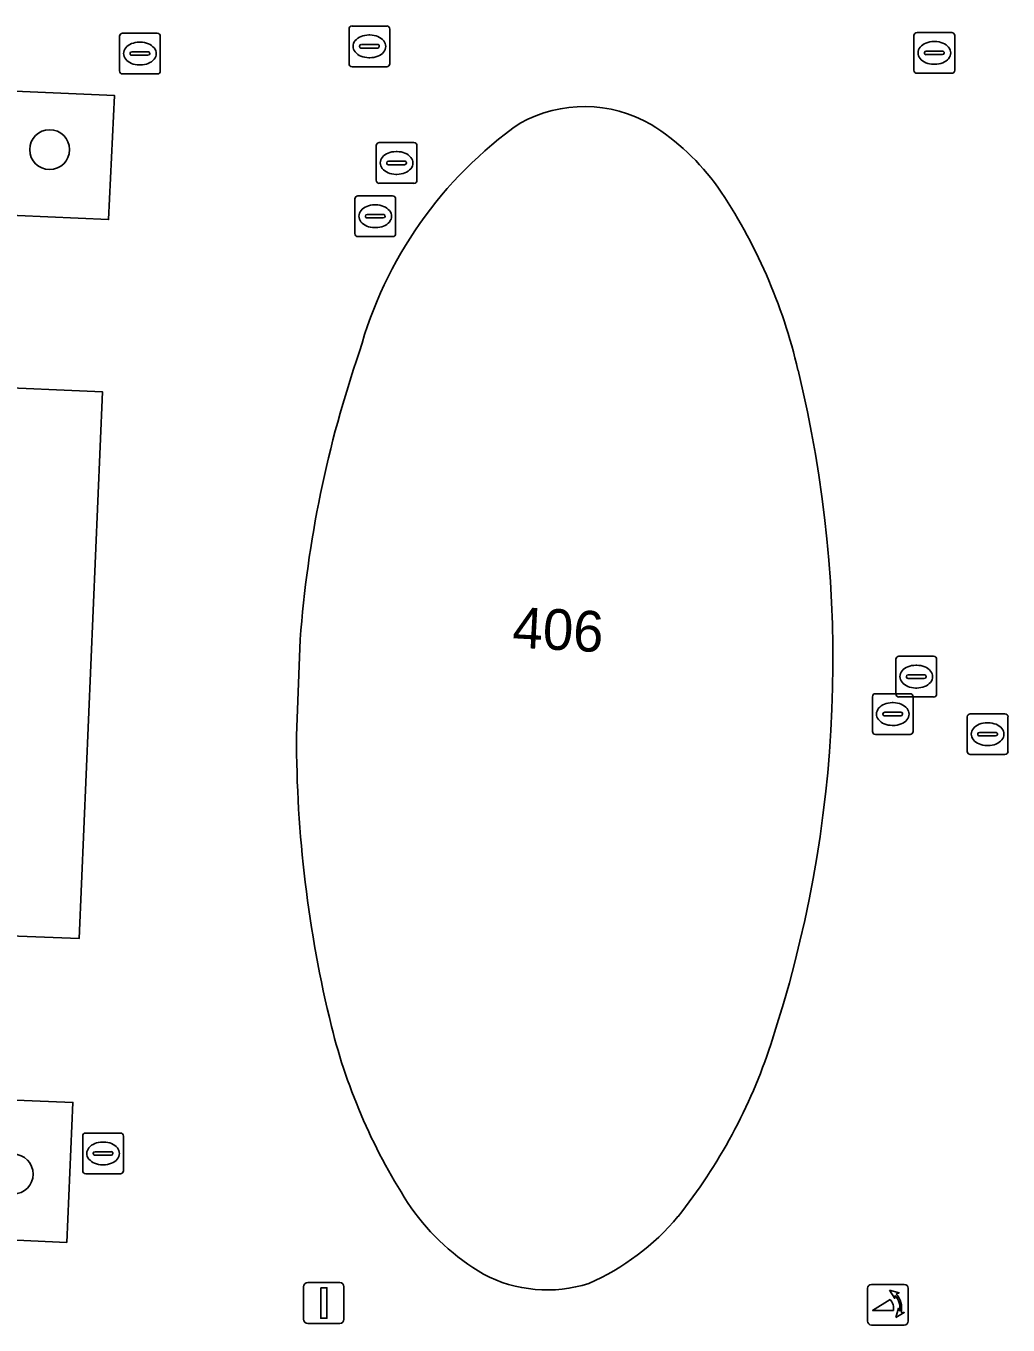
# Model space of a CAD drawing. Extents: x 160888 to 161385, y 386490 to 386908.
# Drawn here: x 161040.48 to 161064.6, y 386705.3 to 386737.22 of the extents above; entities that cross this region are included whole.
import ezdxf

# ---------------------------------------------------------------- set-up
doc = ezdxf.new("R2010")
doc.units = 0
for name, color, linetype in [('IMGEO_Boom', 7, 'Continuous'), ('IMGEO_Groenvoorziening', 7, 'Continuous'), ('IMGEO_Kolk', 7, 'Continuous'), ('IMGEO_Lichtmast', 7, 'Continuous'), ('IMGEO_Pand', 7, 'Continuous'), ('IMGEO_Pand_nummerreeks', 7, 'Continuous'), ('IMGEO_Poller', 7, 'Continuous'), ('IMGEO_Rioolput', 7, 'Continuous'), ('IMGEO_Voetpad_open', 7, 'Continuous')]:
    doc.layers.add(name, color=color, linetype=linetype)

msp = doc.modelspace()

# ---------------------------------------------------------------- linework, layer by layer
at = {"layer": 'IMGEO_Boom'}
for centre in [(161041.064, 386734.18), (161040.172, 386709.011)]:
    msp.add_circle(centre, 0.489, dxfattribs=at)
at = {"layer": 'IMGEO_Groenvoorziening'}
for points in [[(161039.526, 386732.596), (161042.513, 386732.464), (161042.656, 386735.511), (161039.638, 386735.641)], [(161038.802, 386714.912), (161041.789, 386714.797), (161042.363, 386728.229), (161039.349, 386728.359)], [(161038.486, 386707.47), (161041.484, 386707.334), (161041.637, 386710.771), (161038.63, 386710.889)]]:
    msp.add_lwpolyline(points, close=True, dxfattribs=at)
at = {"layer": 'IMGEO_Kolk'}
for p, q in [((161048.492, 386737.218), (161049.344, 386737.218)), ((161048.417, 386736.292), (161048.417, 386737.144)), ((161048.905, 386736.998), (161048.93, 386736.998)), ((161049.418, 386737.144), (161049.418, 386736.292)), ((161062.29, 386736.131), (161062.29, 386736.983)), ((161062.365, 386737.057), (161063.217, 386737.057)), ((161063.291, 386736.983), (161063.291, 386736.131)), ((161048.676, 386736.712), (161048.676, 386736.724)), ((161049.114, 386736.675), (161048.716, 386736.675)), ((161048.719, 386736.761), (161049.117, 386736.761)), ((161049.16, 386736.724), (161049.16, 386736.712)), ((161062.549, 386736.551), (161062.549, 386736.563)), ((161062.592, 386736.6), (161062.99, 386736.6)), ((161062.778, 386736.837), (161062.803, 386736.837)), ((161063.033, 386736.563), (161063.033, 386736.551)), ((161048.928, 386736.438), (161048.903, 386736.438)), ((161062.987, 386736.514), (161062.589, 386736.514)), ((161062.801, 386736.277), (161062.776, 386736.277)), ((161049.344, 386736.218), (161048.492, 386736.218)), ((161063.217, 386736.057), (161062.365, 386736.057)), ((161061.269, 386719.888), (161061.269, 386720.74)), ((161061.344, 386720.814), (161062.196, 386720.814)), ((161061.757, 386720.594), (161061.782, 386720.594)), ((161062.27, 386720.74), (161062.27, 386719.888)), ((161061.528, 386720.308), (161061.528, 386720.32)), ((161061.966, 386720.271), (161061.568, 386720.271)), ((161061.571, 386720.357), (161061.969, 386720.357)), ((161062.012, 386720.32), (161062.012, 386720.308)), ((161061.78, 386720.034), (161061.755, 386720.034)), ((161062.196, 386719.814), (161061.344, 386719.814))]:
    msp.add_line(p, q, dxfattribs=at)
for points in [[(161048.492, 386737.218), (161049.344, 386737.218)], [(161048.417, 386736.292), (161048.417, 386737.144)], [(161049.418, 386737.144), (161049.418, 386736.292)], [(161062.29, 386736.131), (161062.29, 386736.983)], [(161062.365, 386737.057), (161063.217, 386737.057)], [(161063.291, 386736.983), (161063.291, 386736.131)], [(161049.344, 386736.218), (161048.492, 386736.218)], [(161063.217, 386736.057), (161062.365, 386736.057)], [(161061.269, 386719.888), (161061.269, 386720.74)], [(161061.344, 386720.814), (161062.196, 386720.814)], [(161062.27, 386720.74), (161062.27, 386719.888)], [(161062.196, 386719.814), (161061.344, 386719.814)]]:
    msp.add_lwpolyline(points, dxfattribs=at)
for centre, radius, start, end in [((161048.494, 386737.142), 0.0765, 91.552, 178.448), ((161048.494, 386737.142), 0.0765, 91.552, 178.448), ((161049.342, 386737.142), 0.0765, 1.552, 88.448), ((161049.342, 386737.142), 0.0765, 1.552, 88.448), ((161062.367, 386736.981), 0.0765, 91.552, 178.448), ((161062.367, 386736.981), 0.0765, 91.552, 178.448), ((161063.215, 386736.981), 0.0765, 1.552, 88.448), ((161063.215, 386736.981), 0.0765, 1.552, 88.448), ((161048.716, 386736.721), 0.0403, 85.8775, 175.7526), ((161048.713, 386736.711), 0.0366, 178.938, 274.7102), ((161049.117, 386736.718), 0.043, 264.8664, 352.4533), ((161049.121, 386736.723), 0.0386, 1.7309, 96.639), ((161062.589, 386736.56), 0.0403, 85.8775, 175.7526), ((161062.586, 386736.55), 0.0366, 178.938, 274.7102), ((161062.99, 386736.557), 0.043, 264.8664, 352.4533), ((161062.994, 386736.562), 0.0386, 1.7309, 96.639), ((161048.494, 386736.294), 0.0765, 181.552, 268.448), ((161048.494, 386736.294), 0.0765, 181.552, 268.448), ((161049.342, 386736.294), 0.0765, 271.552, 358.448), ((161049.342, 386736.294), 0.0765, 271.552, 358.448), ((161062.367, 386736.133), 0.0765, 181.552, 268.448), ((161062.367, 386736.133), 0.0765, 181.552, 268.448), ((161063.215, 386736.133), 0.0765, 271.552, 358.448), ((161063.215, 386736.133), 0.0765, 271.552, 358.448), ((161061.346, 386720.738), 0.0765, 91.552, 178.448), ((161061.346, 386720.738), 0.0765, 91.552, 178.448), ((161062.194, 386720.738), 0.0765, 1.552, 88.448), ((161062.194, 386720.738), 0.0765, 1.552, 88.448), ((161061.568, 386720.317), 0.0403, 85.8775, 175.7526), ((161061.565, 386720.307), 0.0366, 178.938, 274.7102), ((161061.969, 386720.314), 0.043, 264.8664, 352.4533), ((161061.973, 386720.319), 0.0386, 1.7309, 96.639), ((161061.346, 386719.89), 0.0765, 181.552, 268.448), ((161061.346, 386719.89), 0.0765, 181.552, 268.448), ((161062.194, 386719.89), 0.0765, 271.552, 358.448), ((161062.194, 386719.89), 0.0765, 271.552, 358.448)]:
    msp.add_arc(centre, radius, start, end, dxfattribs=at)
for centre, major_axis, ratio, start_param, end_param in [((161048.904, 386736.718), (-0.387, 0.002), 0.722429, 4.712389, 7.853982), ((161048.929, 386736.718), (-0.39, 0.002), 0.717154, 1.570796, 4.712389), ((161062.777, 386736.557), (-0.387, 0.002), 0.722429, 4.712389, 7.853982), ((161062.802, 386736.557), (-0.39, 0.002), 0.717154, 1.570796, 4.712389), ((161061.756, 386720.314), (-0.387, 0.002), 0.722429, 4.712389, 7.853982), ((161061.781, 386720.314), (-0.39, 0.002), 0.717154, 1.570796, 4.712389)]:
    msp.add_ellipse(centre, major_axis=major_axis, ratio=ratio, start_param=start_param, end_param=end_param, dxfattribs=at)
at = {"layer": 'IMGEO_Lichtmast'}
for p, q in [((161047.302, 386705.444), (161047.302, 386706.244)), ((161047.302, 386706.244), (161047.302, 386705.444)), ((161047.402, 386706.344), (161048.192, 386706.344)), ((161048.192, 386706.344), (161047.402, 386706.344)), ((161048.292, 386706.244), (161048.292, 386705.444)), ((161048.292, 386705.444), (161048.292, 386706.244)), ((161048.192, 386705.344), (161047.402, 386705.344)), ((161047.402, 386705.344), (161048.192, 386705.344))]:
    msp.add_line(p, q, dxfattribs=at)
msp.add_lwpolyline([(161047.722, 386706.219), (161047.872, 386706.219), (161047.872, 386705.469), (161047.722, 386705.469), (161047.722, 386706.219)], dxfattribs=at)
for centre, start, end in [((161047.402, 386706.244), 90, 180), ((161047.402, 386706.244), 90, 180), ((161048.192, 386706.244), 0, 90), ((161048.192, 386706.244), 360, 90), ((161047.402, 386705.444), 180, 270), ((161047.402, 386705.444), 180, 270), ((161048.192, 386705.444), 270, 0), ((161048.192, 386705.444), 270, 0)]:
    msp.add_arc(centre, 0.1, start, end, dxfattribs=at)
at = {"layer": 'IMGEO_Pand'}
msp.add_lwpolyline([(161047.22, 386722.145), (161047.127, 386719.777)], dxfattribs=at)
for centre, radius, start, end in [((161054.196, 386731.963), 3.275, 59.9847, 118.8039), ((161058.492, 386726.517), 10.182, 125.2343, 164.6202), ((161052.785, 386729.913), 5.759, 35.5324, 58.0373), ((161046.426, 386725.74), 13.363, 13.0848, 34.2475), ((161074.964, 386720.123), 27.818, 160.9175, 175.8307), ((161030.326, 386721.647), 29.974, 341.6232, 13.7384), ((161077.018, 386719.752), 29.891, 179.953, 193.7693), ((161061.976, 386716.123), 14.418, 193.9898, 213.4039), ((161045.912, 386716.393), 13.527, 321.4821, 341.9293), ((161054.654, 386711.527), 5.778, 215.3302, 239.4389), ((161051.945, 386711.745), 5.912, 293.5352, 320.3134), ((161053.283, 386709.533), 3.368, 242.2634, 287.6749)]:
    msp.add_arc(centre, radius, start, end, dxfattribs=at)
at = {"layer": 'IMGEO_Poller'}
for p, q in [((161062.053, 386706.3), (161061.245, 386706.3)), ((161062.053, 386706.3), (161061.245, 386706.3)), ((161061.151, 386706.205), (161061.151, 386705.398)), ((161061.151, 386706.205), (161061.151, 386705.398)), ((161062.147, 386705.398), (161062.147, 386706.205)), ((161062.147, 386705.398), (161062.147, 386706.205)), ((161061.245, 386705.303), (161062.053, 386705.303)), ((161061.245, 386705.303), (161062.053, 386705.303))]:
    msp.add_line(p, q, dxfattribs=at)
for points in [[(161061.786, 386705.656), (161061.273, 386705.656), (161061.703, 386705.931)], [(161061.83, 386706.029), (161061.818, 386705.956), (161061.693, 386706.161)], [(161061.693, 386706.161), (161061.924, 386706.095), (161061.853, 386706.063)], [(161061.846, 386705.484), (161061.912, 386705.715), (161061.942, 386705.647)], [(161061.978, 386705.62), (161062.05, 386705.609), (161061.846, 386705.484)]]:
    msp.add_lwpolyline(points, dxfattribs=at)
for centre, radius, start, end in [((161061.245, 386706.205), 0.0946, 90, 180), ((161061.245, 386706.205), 0.0946, 90, 180), ((161062.053, 386706.205), 0.0946, 0, 90), ((161062.053, 386706.205), 0.0946, 0, 90), ((161061.458, 386705.706), 0.332, 351.3247, 42.4854), ((161061.472, 386705.716), 0.476, 351.7527, 41.1691), ((161061.472, 386705.716), 0.516, 349.3569, 42.2912), ((161061.245, 386705.398), 0.0946, 180, 270), ((161061.245, 386705.398), 0.0946, 180, 270), ((161062.053, 386705.398), 0.0946, 270, 0), ((161062.053, 386705.398), 0.0946, 270, 0)]:
    msp.add_arc(centre, radius, start, end, dxfattribs=at)
at = {"layer": 'IMGEO_Rioolput'}
for p, q in [((161042.781, 386736.115), (161042.781, 386736.967)), ((161042.856, 386737.041), (161043.708, 386737.041)), ((161043.782, 386736.967), (161043.782, 386736.115)), ((161043.04, 386736.535), (161043.04, 386736.547)), ((161043.083, 386736.584), (161043.481, 386736.584)), ((161043.269, 386736.821), (161043.294, 386736.821)), ((161043.524, 386736.547), (161043.524, 386736.535)), ((161043.478, 386736.498), (161043.08, 386736.498)), ((161043.292, 386736.261), (161043.267, 386736.261)), ((161043.708, 386736.041), (161042.856, 386736.041)), ((161049.158, 386734.353), (161050.01, 386734.353)), ((161049.083, 386733.427), (161049.083, 386734.279)), ((161049.571, 386734.133), (161049.596, 386734.133)), ((161050.084, 386734.279), (161050.084, 386733.427)), ((161049.342, 386733.847), (161049.342, 386733.859)), ((161049.78, 386733.81), (161049.382, 386733.81)), ((161049.385, 386733.896), (161049.783, 386733.896)), ((161049.826, 386733.859), (161049.826, 386733.847)), ((161049.594, 386733.573), (161049.569, 386733.573)), ((161048.634, 386733.044), (161049.486, 386733.044)), ((161050.01, 386733.353), (161049.158, 386733.353)), ((161048.559, 386732.118), (161048.559, 386732.97)), ((161049.047, 386732.824), (161049.072, 386732.824)), ((161049.56, 386732.97), (161049.56, 386732.118)), ((161048.818, 386732.538), (161048.818, 386732.55)), ((161049.256, 386732.501), (161048.858, 386732.501)), ((161048.861, 386732.587), (161049.259, 386732.587)), ((161049.302, 386732.55), (161049.302, 386732.538)), ((161049.07, 386732.264), (161049.045, 386732.264)), ((161049.486, 386732.044), (161048.634, 386732.044)), ((161061.846, 386720.807), (161061.846, 386721.659)), ((161061.921, 386721.733), (161062.773, 386721.733)), ((161062.847, 386721.659), (161062.847, 386720.807)), ((161062.105, 386721.227), (161062.105, 386721.239)), ((161062.148, 386721.276), (161062.546, 386721.276)), ((161062.334, 386721.513), (161062.359, 386721.513)), ((161062.589, 386721.239), (161062.589, 386721.227)), ((161062.543, 386721.19), (161062.145, 386721.19)), ((161062.357, 386720.953), (161062.332, 386720.953)), ((161062.773, 386720.733), (161061.921, 386720.733)), ((161063.673, 386720.32), (161064.525, 386720.32)), ((161063.598, 386719.394), (161063.598, 386720.246)), ((161064.086, 386720.1), (161064.111, 386720.1)), ((161064.599, 386720.246), (161064.599, 386719.394)), ((161063.857, 386719.814), (161063.857, 386719.826)), ((161064.295, 386719.777), (161063.897, 386719.777)), ((161063.9, 386719.863), (161064.298, 386719.863)), ((161064.341, 386719.826), (161064.341, 386719.814)), ((161064.525, 386719.32), (161063.673, 386719.32)), ((161064.109, 386719.54), (161064.084, 386719.54)), ((161041.877, 386709.093), (161041.877, 386709.945)), ((161041.952, 386710.019), (161042.804, 386710.019)), ((161042.365, 386709.799), (161042.39, 386709.799)), ((161042.878, 386709.945), (161042.878, 386709.093)), ((161042.136, 386709.513), (161042.136, 386709.525)), ((161042.574, 386709.476), (161042.176, 386709.476)), ((161042.179, 386709.562), (161042.577, 386709.562)), ((161042.62, 386709.525), (161042.62, 386709.513)), ((161042.388, 386709.239), (161042.363, 386709.239)), ((161042.804, 386709.019), (161041.952, 386709.019))]:
    msp.add_line(p, q, dxfattribs=at)
for points in [[(161042.781, 386736.115), (161042.781, 386736.967)], [(161042.856, 386737.041), (161043.708, 386737.041)], [(161043.782, 386736.967), (161043.782, 386736.115)], [(161043.708, 386736.041), (161042.856, 386736.041)], [(161049.158, 386734.353), (161050.01, 386734.353)], [(161049.083, 386733.427), (161049.083, 386734.279)], [(161050.084, 386734.279), (161050.084, 386733.427)], [(161048.634, 386733.044), (161049.486, 386733.044)], [(161050.01, 386733.353), (161049.158, 386733.353)], [(161048.559, 386732.118), (161048.559, 386732.97)], [(161049.56, 386732.97), (161049.56, 386732.118)], [(161049.486, 386732.044), (161048.634, 386732.044)], [(161061.846, 386720.807), (161061.846, 386721.659)], [(161061.921, 386721.733), (161062.773, 386721.733)], [(161062.847, 386721.659), (161062.847, 386720.807)], [(161062.773, 386720.733), (161061.921, 386720.733)], [(161063.673, 386720.32), (161064.525, 386720.32)], [(161063.598, 386719.394), (161063.598, 386720.246)], [(161064.599, 386720.246), (161064.599, 386719.394)], [(161064.525, 386719.32), (161063.673, 386719.32)], [(161041.877, 386709.093), (161041.877, 386709.945)], [(161041.952, 386710.019), (161042.804, 386710.019)], [(161042.878, 386709.945), (161042.878, 386709.093)], [(161042.804, 386709.019), (161041.952, 386709.019)]]:
    msp.add_lwpolyline(points, dxfattribs=at)
for centre, radius, start, end in [((161042.858, 386736.965), 0.0765, 91.552, 178.448), ((161042.858, 386736.965), 0.0765, 91.552, 178.448), ((161043.706, 386736.965), 0.0765, 1.552, 88.448), ((161043.706, 386736.965), 0.0765, 1.552, 88.448), ((161043.08, 386736.544), 0.0403, 85.8775, 175.7526), ((161043.485, 386736.546), 0.0386, 1.7309, 96.639), ((161043.077, 386736.534), 0.0366, 178.938, 274.7102), ((161043.481, 386736.541), 0.043, 264.8664, 352.4533), ((161042.858, 386736.117), 0.0765, 181.552, 268.448), ((161042.858, 386736.117), 0.0765, 181.552, 268.448), ((161043.706, 386736.117), 0.0765, 271.552, 358.448), ((161043.706, 386736.117), 0.0765, 271.552, 358.448), ((161049.16, 386734.277), 0.0765, 91.552, 178.448), ((161049.16, 386734.277), 0.0765, 91.552, 178.448), ((161050.008, 386734.277), 0.0765, 1.552, 88.448), ((161050.008, 386734.277), 0.0765, 1.552, 88.448), ((161049.382, 386733.856), 0.0403, 85.8775, 175.7526), ((161049.379, 386733.846), 0.0366, 178.938, 274.7102), ((161049.783, 386733.853), 0.043, 264.8664, 352.4533), ((161049.787, 386733.858), 0.0386, 1.7309, 96.639), ((161049.16, 386733.429), 0.0765, 181.552, 268.448), ((161049.16, 386733.429), 0.0765, 181.552, 268.448), ((161050.008, 386733.429), 0.0765, 271.552, 358.448), ((161050.008, 386733.429), 0.0765, 271.552, 358.448), ((161048.636, 386732.968), 0.0765, 91.552, 178.448), ((161048.636, 386732.968), 0.0765, 91.552, 178.448), ((161049.484, 386732.968), 0.0765, 1.552, 88.448), ((161049.484, 386732.968), 0.0765, 1.552, 88.448), ((161048.858, 386732.547), 0.0403, 85.8775, 175.7526), ((161048.855, 386732.537), 0.0366, 178.938, 274.7102), ((161049.259, 386732.544), 0.043, 264.8664, 352.4533), ((161049.263, 386732.549), 0.0386, 1.7309, 96.639), ((161048.636, 386732.12), 0.0765, 181.552, 268.448), ((161048.636, 386732.12), 0.0765, 181.552, 268.448), ((161049.484, 386732.12), 0.0765, 271.552, 358.448), ((161049.484, 386732.12), 0.0765, 271.552, 358.448), ((161061.923, 386721.657), 0.0765, 91.552, 178.448), ((161061.923, 386721.657), 0.0765, 91.552, 178.448), ((161062.771, 386721.657), 0.0765, 1.552, 88.448), ((161062.771, 386721.657), 0.0765, 1.552, 88.448), ((161062.145, 386721.236), 0.0403, 85.8775, 175.7526), ((161062.55, 386721.238), 0.0386, 1.7309, 96.639), ((161062.142, 386721.226), 0.0366, 178.938, 274.7102), ((161062.546, 386721.233), 0.043, 264.8664, 352.4533), ((161061.923, 386720.809), 0.0765, 181.552, 268.448), ((161061.923, 386720.809), 0.0765, 181.552, 268.448), ((161062.771, 386720.809), 0.0765, 271.552, 358.448), ((161062.771, 386720.809), 0.0765, 271.552, 358.448), ((161063.675, 386720.244), 0.0765, 91.552, 178.448), ((161063.675, 386720.244), 0.0765, 91.552, 178.448), ((161064.523, 386720.244), 0.0765, 1.552, 88.448), ((161064.523, 386720.244), 0.0765, 1.552, 88.448), ((161063.897, 386719.823), 0.0403, 85.8775, 175.7526), ((161063.894, 386719.813), 0.0366, 178.938, 274.7102), ((161064.298, 386719.82), 0.043, 264.8664, 352.4533), ((161064.302, 386719.825), 0.0386, 1.7309, 96.639), ((161063.675, 386719.396), 0.0765, 181.552, 268.448), ((161063.675, 386719.396), 0.0765, 181.552, 268.448), ((161064.523, 386719.396), 0.0765, 271.552, 358.448), ((161064.523, 386719.396), 0.0765, 271.552, 358.448), ((161041.954, 386709.943), 0.0765, 91.552, 178.448), ((161041.954, 386709.943), 0.0765, 91.552, 178.448), ((161042.802, 386709.943), 0.0765, 1.552, 88.448), ((161042.802, 386709.943), 0.0765, 1.552, 88.448), ((161042.176, 386709.522), 0.0403, 85.8775, 175.7526), ((161042.173, 386709.512), 0.0366, 178.938, 274.7102), ((161042.577, 386709.519), 0.043, 264.8664, 352.4533), ((161042.581, 386709.524), 0.0386, 1.7309, 96.639), ((161041.954, 386709.095), 0.0765, 181.552, 268.448), ((161041.954, 386709.095), 0.0765, 181.552, 268.448), ((161042.802, 386709.095), 0.0765, 271.552, 358.448), ((161042.802, 386709.095), 0.0765, 271.552, 358.448)]:
    msp.add_arc(centre, radius, start, end, dxfattribs=at)
for centre, major_axis, ratio, start_param, end_param in [((161043.268, 386736.541), (-0.387, 0.002), 0.722429, 4.712389, 7.853982), ((161043.293, 386736.541), (-0.39, 0.002), 0.717154, 1.570796, 4.712389), ((161049.57, 386733.853), (-0.387, 0.002), 0.722429, 4.712389, 7.853982), ((161049.595, 386733.853), (-0.39, 0.002), 0.717154, 1.570796, 4.712389), ((161049.046, 386732.544), (-0.387, 0.002), 0.722429, 4.712389, 7.853982), ((161049.071, 386732.544), (-0.39, 0.002), 0.717154, 1.570796, 4.712389), ((161062.333, 386721.233), (-0.387, 0.002), 0.722429, 4.712389, 7.853982), ((161062.358, 386721.233), (-0.39, 0.002), 0.717154, 1.570796, 4.712389), ((161064.085, 386719.82), (-0.387, 0.002), 0.722429, 4.712389, 7.853982), ((161064.11, 386719.82), (-0.39, 0.002), 0.717154, 1.570796, 4.712389), ((161042.364, 386709.519), (-0.387, 0.002), 0.722429, 4.712389, 7.853982), ((161042.389, 386709.519), (-0.39, 0.002), 0.717154, 1.570796, 4.712389)]:
    msp.add_ellipse(centre, major_axis=major_axis, ratio=ratio, start_param=start_param, end_param=end_param, dxfattribs=at)
at = {"layer": 'IMGEO_Voetpad_open'}
for points in [[(161039.526, 386732.596), (161039.638, 386735.641), (161042.656, 386735.511), (161042.513, 386732.464)], [(161041.789, 386714.797), (161038.802, 386714.912), (161039.349, 386728.359), (161042.363, 386728.229)], [(161041.484, 386707.334), (161038.486, 386707.47), (161038.63, 386710.889), (161041.637, 386710.771)]]:
    msp.add_lwpolyline(points, close=True, dxfattribs=at)
msp.add_lwpolyline([(161047.127, 386719.777), (161047.22, 386722.145)], dxfattribs=at)
for centre, radius, start, end in [((161054.196, 386731.963), 3.275, 59.9847, 118.8039), ((161058.492, 386726.517), 10.182, 125.2343, 164.6202), ((161052.785, 386729.913), 5.759, 35.5324, 58.0373), ((161046.426, 386725.74), 13.363, 13.0848, 34.2475), ((161074.964, 386720.123), 27.818, 160.9175, 175.8307), ((161030.326, 386721.647), 29.974, 341.6232, 13.7384), ((161077.018, 386719.752), 29.891, 179.953, 193.7693), ((161061.976, 386716.123), 14.418, 193.9898, 213.4039), ((161045.912, 386716.393), 13.527, 321.4821, 341.9293), ((161054.654, 386711.527), 5.778, 215.3302, 239.4389), ((161051.945, 386711.745), 5.912, 293.5352, 320.3134), ((161053.283, 386709.533), 3.368, 242.2634, 287.6749)]:
    msp.add_arc(centre, radius, start, end, dxfattribs=at)

# ---------------------------------------------------------------- texts
at = {"layer": 'IMGEO_Pand_nummerreeks'}
msp.add_text('406', height=1, rotation=356.8911, dxfattribs=at).set_placement((161052.412, 386721.951))

doc.saveas('drawing.dxf')
